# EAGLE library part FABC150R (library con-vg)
CONNECTOR female, 150 pins, type R, rows ABC, grid 2.54 mm
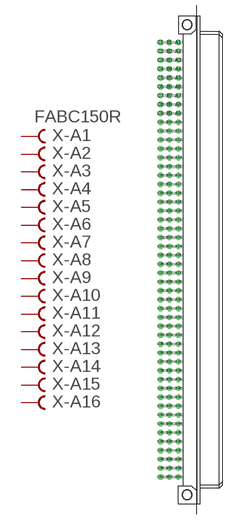
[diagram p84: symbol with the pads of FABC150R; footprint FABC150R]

Designator prefix X; gates -A1=FVAL -A2=FEM -A3=FEM -A4=FEM -A5=FEM -A6=FEM -A7=FEM -A8=FEM -A9=FEM -A10=FEM -A11=FEM -A12=FEM -A13=FEM -A14=FEM -A15=FEM -A16=FEM -A17=FEM -A18=FEM -A19=FEM -A20=FEM -A21=FEM -A22=FEM -A23=FEM -A24=FEM -A25=FEM -A26=FEM -A27=FEM -A28=FEM -A29=FEM -A30=FEM -A31=FEM -A32=FEM -A33=FEM -A34=FEM -A35=FEM -A36=FEM -A37=FEM -A38=FEM -A39=FEM -A40=FEM -A41=FEM -A42=FEM -A43=FEM -A44=FEM -A45=FEM -A46=FEM -A47=FEM -A48=FEM -A49=FEM -A50=FEM -B1=FVAL -B2=FEM -B3=FEM -B4=FEM -B5=FEM -B6=FEM -B7=FEM -B8=FEM -B9=FEM -B10=FEM -B11=FEM -B12=FEM -B13=FEM -B14=FEM -B15=FEM -B16=FEM -B17=FEM -B18=FEM -B19=FEM -B20=FEM -B21=FEM -B22=FEM -B23=FEM -B24=FEM -B25=FEM -B26=FEM -B27=FEM -B28=FEM -B29=FEM -B30=FEM -B31=FEM -B32=FEM -B33=FEM -B34=FEM -B35=FEM -B36=FEM -B37=FEM -B38=FEM -B39=FEM -B40=FEM -B41=FEM -B42=FEM -B43=FEM -B44=FEM -B45=FEM -B46=FEM -B47=FEM -B48=FEM -B49=FEM -B50=FEM -C1=FVAL -C2=FEM -C3=FEM -C4=FEM -C5=FEM -C6=FEM -C7=FEM -C8=FEM -C9=FEM -C10=FEM -C11=FEM -C12=FEM -C13=FEM -C14=FEM -C15=FEM -C16=FEM -C17=FEM -C18=FEM -C19=FEM -C20=FEM -C21=FEM -C22=FEM -C23=FEM -C24=FEM -C25=FEM -C26=FEM -C27=FEM -C28=FEM -C29=FEM -C30=FEM -C31=FEM -C32=FEM -C33=FEM -C34=FEM -C35=FEM -C36=FEM -C37=FEM -C38=FEM -C39=FEM -C40=FEM -C41=FEM -C42=FEM -C43=FEM -C44=FEM -C45=FEM -C46=FEM -C47=FEM -C48=FEM -C49=FEM -C50=FEM

## FABC150R  [FABC150R]
A1  -A1:B  pas
A2  -A2:B  pas
A3  -A3:B  pas
A4  -A4:B  pas
A5  -A5:B  pas
A6  -A6:B  pas
A7  -A7:B  pas
A8  -A8:B  pas
A9  -A9:B  pas
A10  -A10:B  pas
A11  -A11:B  pas
A12  -A12:B  pas
A13  -A13:B  pas
A14  -A14:B  pas
A15  -A15:B  pas
A16  -A16:B  pas
A17  -A17:B  pas
A18  -A18:B  pas
A19  -A19:B  pas
A20  -A20:B  pas
A21  -A21:B  pas
A22  -A22:B  pas
A23  -A23:B  pas
A24  -A24:B  pas
A25  -A25:B  pas
A26  -A26:B  pas
A27  -A27:B  pas
A28  -A28:B  pas
A29  -A29:B  pas
A30  -A30:B  pas
A31  -A31:B  pas
A32  -A32:B  pas
A33  -A33:B  pas
A34  -A34:B  pas
A35  -A35:B  pas
A36  -A36:B  pas
A37  -A37:B  pas
A38  -A38:B  pas
A39  -A39:B  pas
A40  -A40:B  pas
A41  -A41:B  pas
A42  -A42:B  pas
A43  -A43:B  pas
A44  -A44:B  pas
A45  -A45:B  pas
A46  -A46:B  pas
A47  -A47:B  pas
A48  -A48:B  pas
A49  -A49:B  pas
A50  -A50:B  pas
B1  -B1:B  pas
B2  -B2:B  pas
B3  -B3:B  pas
B4  -B4:B  pas
B5  -B5:B  pas
B6  -B6:B  pas
B7  -B7:B  pas
B8  -B8:B  pas
B9  -B9:B  pas
B10  -B10:B  pas
B11  -B11:B  pas
B12  -B12:B  pas
B13  -B13:B  pas
B14  -B14:B  pas
B15  -B15:B  pas
B16  -B16:B  pas
B17  -B17:B  pas
B18  -B18:B  pas
B19  -B19:B  pas
B20  -B20:B  pas
B21  -B21:B  pas
B22  -B22:B  pas
B23  -B23:B  pas
B24  -B24:B  pas
B25  -B25:B  pas
B26  -B26:B  pas
B27  -B27:B  pas
B28  -B28:B  pas
B29  -B29:B  pas
B30  -B30:B  pas
B31  -B31:B  pas
B32  -B32:B  pas
B33  -B33:B  pas
B34  -B34:B  pas
B35  -B35:B  pas
B36  -B36:B  pas
B37  -B37:B  pas
B38  -B38:B  pas
B39  -B39:B  pas
B40  -B40:B  pas
B41  -B41:B  pas
B42  -B42:B  pas
B43  -B43:B  pas
B44  -B44:B  pas
B45  -B45:B  pas
B46  -B46:B  pas
B47  -B47:B  pas
B48  -B48:B  pas
B49  -B49:B  pas
B50  -B50:B  pas
C1  -C1:B  pas
C2  -C2:B  pas
C3  -C3:B  pas
C4  -C4:B  pas
C5  -C5:B  pas
C6  -C6:B  pas
C7  -C7:B  pas
C8  -C8:B  pas
C9  -C9:B  pas
C10  -C10:B  pas
C11  -C11:B  pas
C12  -C12:B  pas
C13  -C13:B  pas
C14  -C14:B  pas
C15  -C15:B  pas
C16  -C16:B  pas
C17  -C17:B  pas
C18  -C18:B  pas
C19  -C19:B  pas
C20  -C20:B  pas
C21  -C21:B  pas
C22  -C22:B  pas
C23  -C23:B  pas
C24  -C24:B  pas
C25  -C25:B  pas
C26  -C26:B  pas
C27  -C27:B  pas
C28  -C28:B  pas
C29  -C29:B  pas
C30  -C30:B  pas
C31  -C31:B  pas
C32  -C32:B  pas
C33  -C33:B  pas
C34  -C34:B  pas
C35  -C35:B  pas
C36  -C36:B  pas
C37  -C37:B  pas
C38  -C38:B  pas
C39  -C39:B  pas
C40  -C40:B  pas
C41  -C41:B  pas
C42  -C42:B  pas
C43  -C43:B  pas
C44  -C44:B  pas
C45  -C45:B  pas
C46  -C46:B  pas
C47  -C47:B  pas
C48  -C48:B  pas
C49  -C49:B  pas
C50  -C50:B  pas

## Footprint FABC150R (pad centres in mm)
CONNECTOR female, 150 pins, type R, rows ABC, grid 2.54 mm
drill 1.016 octagon: A1 -2.54,62.23; A2 -2.54,59.69; A3 -2.54,57.15; A4 -2.54,54.61; A5 -2.54,52.07; A6 -2.54,49.53; A7 -2.54,46.99; A8 -2.54,44.45; A9 -2.54,41.91; A10 -2.54,39.37; A11 -2.54,36.83; A12 -2.54,34.29; A13 -2.54,31.75; A14 -2.54,29.21; A15 -2.54,26.67; A16 -2.54,24.13; A17 -2.54,21.59; A18 -2.54,19.05; A19 -2.54,16.51; A20 -2.54,13.97; A21 -2.54,11.43; A22 -2.54,8.89; A23 -2.54,6.35; A24 -2.54,3.81; A25 -2.54,1.27; A26 -2.54,-1.27; A27 -2.54,-3.81; A28 -2.54,-6.35; A29 -2.54,-8.89; A30 -2.54,-11.43; A31 -2.54,-13.97; A32 -2.54,-16.51; A33 -2.54,-19.05; A34 -2.54,-21.59; A35 -2.54,-24.13; A36 -2.54,-26.67; A37 -2.54,-29.21; A38 -2.54,-31.75; A39 -2.54,-34.29; A40 -2.54,-36.83; A41 -2.54,-39.37; A42 -2.54,-41.91; A43 -2.54,-44.45; A44 -2.54,-46.99; A45 -2.54,-49.53; A46 -2.54,-52.07; A47 -2.54,-54.61; A48 -2.54,-57.15; A49 -2.54,-59.69; A50 -2.54,-62.23; B1 -5.08,62.23; B2 -5.08,59.69; B3 -5.08,57.15; B4 -5.08,54.61; B5 -5.08,52.07; B6 -5.08,49.53; B7 -5.08,46.99; B8 -5.08,44.45; B9 -5.08,41.91; B10 -5.08,39.37; B11 -5.08,36.83; B12 -5.08,34.29; B13 -5.08,31.75; B14 -5.08,29.21; B15 -5.08,26.67; B16 -5.08,24.13; B17 -5.08,21.59; B18 -5.08,19.05; B19 -5.08,16.51; B20 -5.08,13.97; B21 -5.08,11.43; B22 -5.08,8.89; B23 -5.08,6.35; B24 -5.08,3.81; B25 -5.08,1.27; B26 -5.08,-1.27; B27 -5.08,-3.81; B28 -5.08,-6.35; B29 -5.08,-8.89; B30 -5.08,-11.43; B31 -5.08,-13.97; B32 -5.08,-16.51; B33 -5.08,-19.05; B34 -5.08,-21.59; B35 -5.08,-24.13; B36 -5.08,-26.67; B37 -5.08,-29.21; B38 -5.08,-31.75; B39 -5.08,-34.29; B40 -5.08,-36.83; B41 -5.08,-39.37; B42 -5.08,-41.91; B43 -5.08,-44.45; B44 -5.08,-46.99; B45 -5.08,-49.53; B46 -5.08,-52.07; B47 -5.08,-54.61; B48 -5.08,-57.15; B49 -5.08,-59.69; B50 -5.08,-62.23; C1 -7.62,62.23; C2 -7.62,59.69; C3 -7.62,57.15; C4 -7.62,54.61; C5 -7.62,52.07; C6 -7.62,49.53; C7 -7.62,46.99; C8 -7.62,44.45; C9 -7.62,41.91; C10 -7.62,39.37; C11 -7.62,36.83; C12 -7.62,34.29; C13 -7.62,31.75; C14 -7.62,29.21; C15 -7.62,26.67; C16 -7.62,24.13; C17 -7.62,21.59; C18 -7.62,19.05; C19 -7.62,16.51; C20 -7.62,13.97; C21 -7.62,11.43; C22 -7.62,8.89; C23 -7.62,6.35; C24 -7.62,3.81; C25 -7.62,1.27; C26 -7.62,-1.27; C27 -7.62,-3.81; C28 -7.62,-6.35; C29 -7.62,-8.89; C30 -7.62,-11.43; C31 -7.62,-13.97; C32 -7.62,-16.51; C33 -7.62,-19.05; C34 -7.62,-21.59; C35 -7.62,-24.13; C36 -7.62,-26.67; C37 -7.62,-29.21; C38 -7.62,-31.75; C39 -7.62,-34.29; C40 -7.62,-36.83; C41 -7.62,-39.37; C42 -7.62,-41.91; C43 -7.62,-44.45; C44 -7.62,-46.99; C45 -7.62,-49.53; C46 -7.62,-52.07; C47 -7.62,-54.61; C48 -7.62,-57.15; C49 -7.62,-59.69; C50 -7.62,-62.23
hole 2.794 at 0,-67.316
hole 2.794 at 0,67.316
